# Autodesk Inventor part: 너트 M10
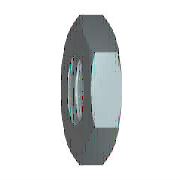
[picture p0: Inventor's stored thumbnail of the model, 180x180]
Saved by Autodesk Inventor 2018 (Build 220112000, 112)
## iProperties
IsCustomPart: 1
Created: 2012-02
Part Number: 너트 M10
Material: 스테인리스강
Description: 미터법 정밀 피치 스레드가 있는 6각 가는 너트(모따기됨)
Document SubType Name: Modeling
Standard: ISO 8675
Designer: mduedu
Standard Revision: Second edition 1999-08-15
Standards Organization: ISO
Language: ko-KR
Size Designation: M10 x 1
Categories: <MemberInstance><Categories><Category DisplayName="조임쇠" InternalName="e4da775c-781d-43d5-af7c-5136215cf5a6" Mnemonic="FSTN"><Category DisplayName="너트" InternalN
Density: 8.08 g/cm^3
Appearance: 기본값
Author: mduedu
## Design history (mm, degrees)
sketch "스케치1"
  geometry: L1 (-9.238, 0)-(-4.619, 8); L2 (-4.619, 8)-(4.619, 8); L3 (4.619, 8)-(9.238, 0); L4 (9.238, 0)-(4.619, -8); L5 (4.619, -8)-(-4.619, -8); L6 (-4.619, -8)-(-9.238, 0); 2 further points
  constraints: 12 end point, 1 coincident, 1 horizontal, 11 other
  dimensions: "d0" = 18.47521 distance of L3.end L1.start (= 1.1547 x SW)
extrude "본체" new body sketch "스케치1" distance "d1" = 5 (= KOH); taper "d2" = 0 deg
sketch "스케치2"
  geometry: L1 (0, 4.619)-(0, 9.238) reference; L2 (0, 9.238)-(5, 9.238) reference; L3 (5, 4.619)-(5, 9.238) reference; L4 (-1, 0)-(6, 0) reference; L5 (1.11, 9.238)-(0, 7.315); L6 (3.89, 9.238)-(5, 7.315)
  constraints: 4 end point, 4 point on line
  dimensions: "d3" = 30 deg angle of L1 L5 (= ANG1); "d4" = 30 deg angle of L3 L6 (= ANG2); "d5" = 14.63 diameter of L5.end L4 (= SW0); "d6" = 14.63 diameter of L6.end L4 (= SW01)
revolve "모따기1" sketch "스케치2" stored, may be unused: angle "d7" = 90 deg
sketch "스케치3"
  geometry: 4 further points
  constraints: 1 coincident, 1 other
hole "스레드" sketch "스케치3" at (0, 0) diameter "d25" = 8.91747; stored, may be unused: countersink angle "d29" = 82 deg, drill point angle "d31" = 118 deg; dims "d26" = 6, "d27" = 4, "d28" = 2, "d30" = 8
workaxis "Work Axis1"
workplane "Work Plane1"
body "Solid1"
chamfer "모따기2" distance "d8" = 0.54127 (= -0.5 x GD1 + 0.5 x NND); stored, may be unused: angle "d9" = 30 deg, second distance "d40" = 0.54127 (= -0.5 x GD1 + 0.5 x NND)
chamfer "모따기3" distance "d10" = 0.54127 (= -0.5 x GD1 + 0.5 x NND); stored, may be unused: angle "d11" = 30 deg, second distance "d41" = 0.54127 (= -0.5 x GD1 + 0.5 x NND)
other parameters: "ANG1" = 30 deg [user parameter; used in 1 equation term], "ANG2" = 30 deg [user parameter; used in 1 equation term], "KOH" = 5 [user parameter; used in 1 equation term], "SW" = 16 [user parameter; used in 1 equation term], "SW0" = 14.63 [user parameter; used in 2 equation terms], "SW01" = 14.63 (= SW0) [user parameter; used in 1 equation term], "GD1" = 8.91747 (computed from THREADDIA, PTC, TOA) [user parameter; used in 4 equation terms], "d13" = 0, "d14" = 0, "d39" = 0, "d42" = 0, "GUL" = 0.54127 (= 0.541266 x PTC) [user parameter], "TOA" = 30 deg [user parameter; used in 1 equation term], "PTC" = 1 [user parameter; used in 4 equation terms], "E0" = 17.77 [user parameter], "GAL" = 0.54127 (= 0.541266 x PTC) [user parameter]
